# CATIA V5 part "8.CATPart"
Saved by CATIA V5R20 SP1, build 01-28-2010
Part number: 8
Publications: "C", "Droite.1", "Droite.2", "Droite.3", "Droite.7", "Droite.6", "Droite.5", "C1", "B", "Droite.8", "Droite.9", "Droite.10", "Plan.3", "Point.26", "Droite.101"
Bounding box of the stored display mesh (mm): x -50 to 50, y 66.751 to 76.611, z -20.984 to 26.851
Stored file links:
  F:\TRAV\IAO\Exercice IAO\Catia\8.CATPart
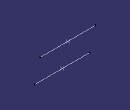
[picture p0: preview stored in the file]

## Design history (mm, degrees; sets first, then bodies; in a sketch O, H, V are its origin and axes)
Parameters
  BC = 50 mm
  HK = 50 mm
  GH = 120 mm
Body1 (main body)
  Point1 "B": stored without definition
  Sketch1 on yz-plane, origin (0, 0, 0), H (0, 1, 0), V (0, 0, 1)
    circle A1 centre (47.9625, -14.128) radius 50
    point P1 (47.9625, -14.128)
    reference projected point E1 (47.9625, -14.128) from Point1
    radius A1 = 50
    coincidence: E1 P1
  Point2 "C": stored without definition
  Point3 "C": (0, 0, 0), relative to Point2
  Point4 "B": stored without definition
  Line1: type PtDir, RefPoint Point3, Direction yz-plane, Start -50, End 50
  Point5 "K": stored without definition
  Point6 "K": stored without definition
  Point7 "B": stored without definition
  Plane1: type Offset, RefPlane yz-plane, Offset 0
  Point8 "B": stored without definition
  Point9: (0, 0, 0), relative to Point8
  Line2: type PtDir, RefPoint Point9, Direction Line1, Start -50, End 50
